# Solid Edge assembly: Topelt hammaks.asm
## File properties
Author: Türk
Template: Iso Assembly.asm
Last saved by: Türk
Revision: 5
Application: Solid Edge
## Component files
40X hammasratas.par
16X hammasratas2.par
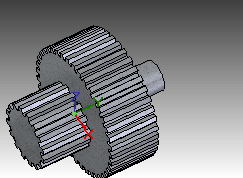
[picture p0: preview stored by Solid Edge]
